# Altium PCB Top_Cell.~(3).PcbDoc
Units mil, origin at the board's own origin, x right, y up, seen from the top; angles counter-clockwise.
Board outline 10125.98 x 3113.96 mil, 2 copper layers (Top Layer, Bottom Layer); 38 components, 15 nets, 104 pads, 0 vias.
Unrouted connection lines stored in the file: 81.
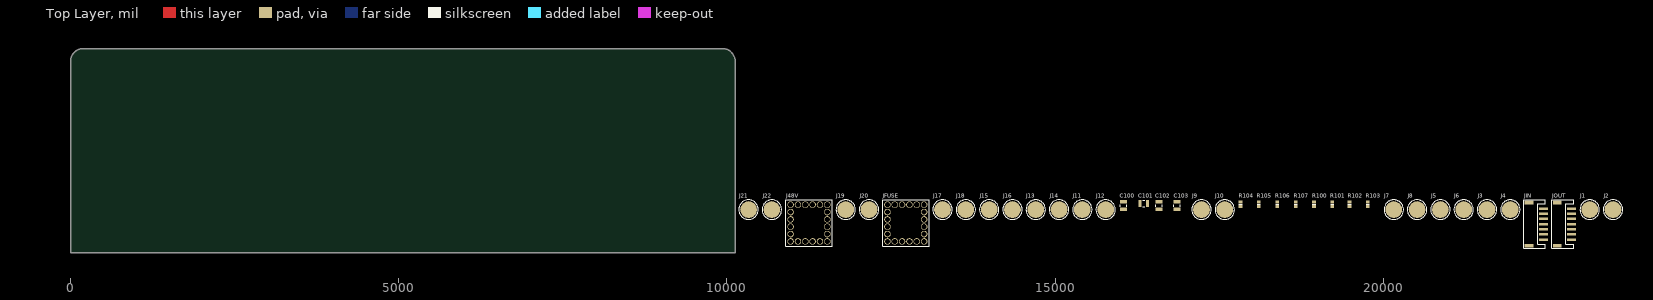
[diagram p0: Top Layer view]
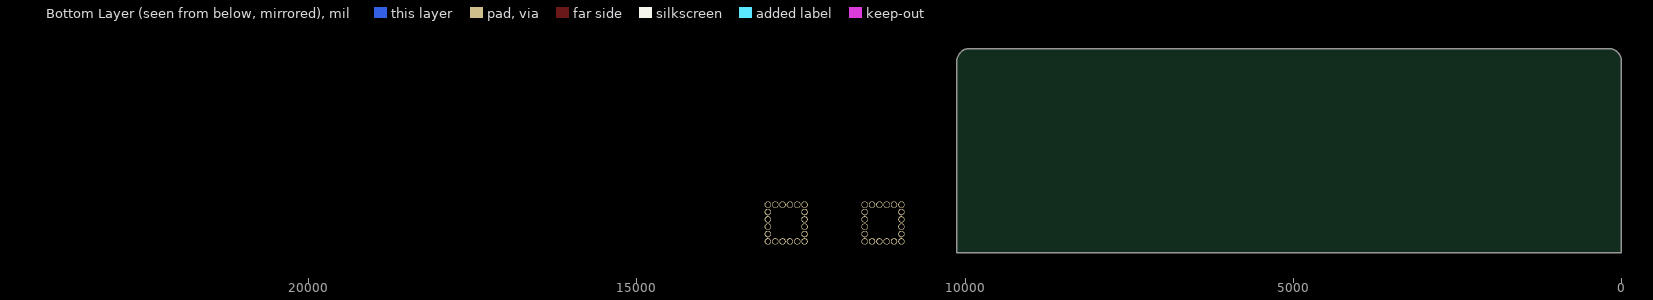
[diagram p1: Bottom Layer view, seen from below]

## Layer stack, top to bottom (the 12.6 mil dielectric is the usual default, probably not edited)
Top Solder: solder mask 0.4, Solder Resist, Dk 3.5
Top Layer: signal copper 1.4
Dielectric 1: dielectric 12.6, FR-4, Dk 4.8
Bottom Layer: signal copper 1.4
Bottom Solder: solder mask 0.4, Solder Resist, Dk 3.5

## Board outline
0.5,389.5 10126.48,389.5 10126.48,3306.61 ccw(c9929.63,3306.61) 9929.63,3503.46 197.35,3503.46 ccw(c197.35,3306.61) 0.5,3306.61

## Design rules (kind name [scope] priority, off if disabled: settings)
Clearance [All] p1: gap=10 ignorepadtopadclearanceinfootprint=FALSE except(0: Arc-Hole Track-Hole SMDPad-Hole THPad-Hole Via-Hole Fill-Hole Poly-Hole Region-Hole Text-Hole)
PolygonConnect [All] p1: connectstyle=Relief reliefconductorwidth=10 reliefentries=4 polygonreliefangle="90 Angle" airgapwidth=10
RoutingVias [All] p1: holewidth=28 width=50 viastyle="Through Hole" minholewidth=28 minwidth=50 maxholewidth=28 maxwidth=50
SolderMaskExpansion [All] p1: expansion=4 istentingtop=FALSE
Width [All] p1: maxlimit=10 minlimit=10 preferedwidth=10
30 further rules are at their usual default settings.

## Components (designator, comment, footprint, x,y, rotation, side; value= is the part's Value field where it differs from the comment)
C100 "C1210C106K3RACAUTO" CAPC3225N 16040,1110 r90 top value=10µF
C101 "C1210C106K3RACAUTO" CAPC3225N 16350,1140 r0 top value=10µF
C102 "C1210C106K3RACAUTO" CAPC3225N 16580,1110 r90 top value=10µF
C103 "C1210C106K3RACAUTO" CAPC3225N 16860,1110 r90 top value=10µF
J1 "2036-3-57-15-00-00-03-0" "6mm Pad" 23145,1050 r0 top
J2 "2036-3-57-15-00-00-03-0" "6mm Pad" 23500,1050 r0 top
J3 "2036-3-57-15-00-00-03-0" "6mm Pad" 21580,1050 r0 top
J4 "2036-3-57-15-00-00-03-0" "6mm Pad" 21935,1050 r0 top
J5 "2036-3-57-15-00-00-03-0" "6mm Pad" 20870,1050 r0 top
J6 "2036-3-57-15-00-00-03-0" "6mm Pad" 21225,1050 r0 top
J7 "2036-3-57-15-00-00-03-0" "6mm Pad" 20160,1050 r0 top
J8 "2036-3-57-15-00-00-03-0" "6mm Pad" 20515,1050 r0 top
J9 "2036-3-57-15-00-00-03-0" "6mm Pad" 17230,1050 r0 top
J10 "2036-3-57-15-00-00-03-0" "6mm Pad" 17585,1050 r0 top
J11 "2036-3-57-15-00-00-03-0" "6mm Pad" 15415,1050 r0 top
J12 "2036-3-57-15-00-00-03-0" "6mm Pad" 15770,1050 r0 top
J13 "2036-3-57-15-00-00-03-0" "6mm Pad" 14705,1050 r0 top
J14 "2036-3-57-15-00-00-03-0" "6mm Pad" 15060,1050 r0 top
J15 "2036-3-57-15-00-00-03-0" "6mm Pad" 13995,1050 r0 top
J16 "2036-3-57-15-00-00-03-0" "6mm Pad" 14350,1050 r0 top
J17 "2036-3-57-15-00-00-03-0" "6mm Pad" 13285,1050 r0 top
J18 "2036-3-57-15-00-00-03-0" "6mm Pad" 13640,1050 r0 top
J19 "2036-3-57-15-00-00-03-0" "6mm Pad" 11810,1050 r0 top
J20 "2036-3-57-15-00-00-03-0" "6mm Pad" 12165,1050 r0 top
J21 "2036-3-57-15-00-00-03-0" "6mm Pad" 10330,1050 r0 top
J22 "2036-3-57-15-00-00-03-0" "6mm Pad" 10685,1050 r0 top
J48V "S98979" S98979 11250,845 r0 top
JFUSE "S98979" S98979 12725,845 r0 top
JIN "S7B-PH-SM4-TB(LF)(SN)" JST-PH-S7 22440,830 r90 top
JOUT "S7B-PH-SM4-TB(LF)(SN)" JST-PH-S7 22870,830 r90 top
R100 "ERJ-6ENF1003V" RESC2012N 18945,1130 r90 top value=100k
R101 "ERJ-6ENF1003V" RESC2012N 19225,1130 r90 top value=100k
R102 "ERJ-6ENF1003V" RESC2012N 19485,1130 r90 top value=100k
R103 "ERJ-6ENF1003V" RESC2012N 19765,1130 r90 top value=100k
R104 "ERJ-6ENF10R0V" RESC2012N 17825,1130 r90 top value=10
R105 "ERJ-6ENF10R0V" RESC2012N 18105,1130 r90 top value=10
R106 "ERJ-6ENF10R0V" RESC2012N 18385,1130 r90 top value=10
R107 "ERJ-6ENF10R0V" RESC2012N 18665,1130 r90 top value=10

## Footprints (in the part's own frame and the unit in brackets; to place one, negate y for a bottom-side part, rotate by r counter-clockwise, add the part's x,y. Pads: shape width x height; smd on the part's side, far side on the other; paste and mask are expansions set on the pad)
"6mm Pad" [mm] "Pad, 6mm"
  round 6.5 smd mask+0.508: 1(0,0)
  silkscreen extent -3.78,-3.77 3.78,3.77, body extent -3,-3 3,3, height 1.4
CAPC3225N [mm] "Chip Capacitor Body 3.2x2.5mm, IPC Medium Density"
  rect 1.3x2.7 smd: 1(-1.45,0) 2(1.45,0)
  silkscreen extent -0.4,-1.25 0.4,1.25, body extent -1.67,-1.32 1.67,1.32, height 1.5
JST-PH-S7 [mm] "Locking Connector; Side-Entry; Header; 7-Pin, 2mm pitch"
  rect 1x3.5 smd: 1(-6,0) 2(-4,0) 3(-2,0) 4(0,0) 5(2,0) 6(4,0) 7(6,0)
  rect 1.5x3.4 smd: 8(-8.382,5.588) 9(8.35,5.55)
  silkscreen extent -9.4,-0.76 9.4,7.62, body extent -8.95,-1.49 8.95,7.11, height 5.5
RESC2012N [mm] "Chip Resistor, Body 2.0x1.2mm, IPC Medium Density"
  rect 1.2x1.4 smd: 1(-0.9,0) 2(0.9,0)
  silkscreen extent 0,-0.6 0,0.6, body extent -1.07,-0.7 1.07,0.7, height 0.7
S98979 [mm] "20 Pin Shank Terminal M8 Through Hole"
  round 2.5 hole 2: 1(-7.1,-7.1) 1(-7.1,-4.26) 1(-7.1,-1.42) 1(-7.1,1.42) 1(-7.1,4.26) 1(-7.1,7.1) 1(-4.26,-7.1) 1(-4.26,7.1) 1(-1.42,-7.1) 1(-1.42,7.1) 1(1.42,-7.1) 1(1.42,7.1) 1(4.26,-7.1) 1(4.26,7.1) 1(7.1,-7.1) 1(7.1,-4.26) 1(7.1,-1.42) 1(7.1,1.42) 1(7.1,4.26) 1(7.1,7.1)
  silkscreen extent -9,-9 9,9, body extent -7.7,-7.7 7.7,7.7, height 31.5

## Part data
C100 C101 C102 C103: "Capacitor, Ceramic, 10µF, 25V, 0805, 10%, 125C", Supplier Part Number 1=399-7046-1-ND, Temp=125C
J1 J2 J3 J4 J5 J6 J7 J8 J9 J10 J11 J12 J13 J14 J15 J16 J17 J18 J19 J20 J21 J22: "Hardware, Sprint Contact Surface", Supplier Part Number 1=54-2036-3-57-15-00-00-03-0CT-ND
J48V JFUSE: "Screw Terminal M8, 360A", Supplier Part Number 1=2101-S98979-ND
JIN JOUT: "Header, JST, 7-Pin, Right-Angle, PH, Surface Mount", Supplier Part Number 1=455-1754-1-ND
R100 R101 R102 R103: "Resistor, Fixed, 100 kOhm, 0805, 1%, 1/8W", Supplier Part Number 1=P100KCCT-ND
R104 R105 R106 R107: "Resistor, Fixed, 10 Ohm, 0805, 1%, 1/8W", Supplier Part Number 1=P10.0CCT-ND

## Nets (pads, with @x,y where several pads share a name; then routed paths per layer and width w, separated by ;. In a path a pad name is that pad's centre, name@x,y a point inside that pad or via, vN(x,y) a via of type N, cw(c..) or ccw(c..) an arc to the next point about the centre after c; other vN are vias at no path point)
SCL: R107.2
SCL_IN: C103.1 JIN.5
SCL_OUT: C103.2 JOUT.3 R103.2 R107.1
SDA: R106.1
SDA_IN: C102.1 JIN.4
SDA_OUT: C102.2 JOUT.4 R102.1 R106.2
ST_CH: R104.1
ST_CH_IN: C100.1 JIN.2
ST_CH_OUT: C100.2 JOUT.6 R100.1 R104.2
ST_DIS: R105.2
ST_DIS_IN: C101.1 JIN.3
ST_DIS_OUT: C101.2 JOUT.5 R101.2 R105.1
VNEG: J1.1 J2.1 J3.1 J4.1 J5.1 J6.1 J7.1 J8.1 J9.1 J10.1 J11.1 J12.1 J13.1 J14.1 J15.1 J16.1 J17.1 J18.1 J19.1 J20.1 J21.1 J22.1 JFUSE.1 JIN.1
VO: J48V.1
VPOS: JOUT.7 R100.2 R101.1 R102.2 R103.1
pads on no net: JIN.6 JIN.7 JIN.8 JIN.9 JOUT.1 JOUT.2 JOUT.8 JOUT.9

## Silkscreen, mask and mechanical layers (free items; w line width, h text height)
Mechanical 1:
  drawing of 160 lines, arcs and shapes, not listed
